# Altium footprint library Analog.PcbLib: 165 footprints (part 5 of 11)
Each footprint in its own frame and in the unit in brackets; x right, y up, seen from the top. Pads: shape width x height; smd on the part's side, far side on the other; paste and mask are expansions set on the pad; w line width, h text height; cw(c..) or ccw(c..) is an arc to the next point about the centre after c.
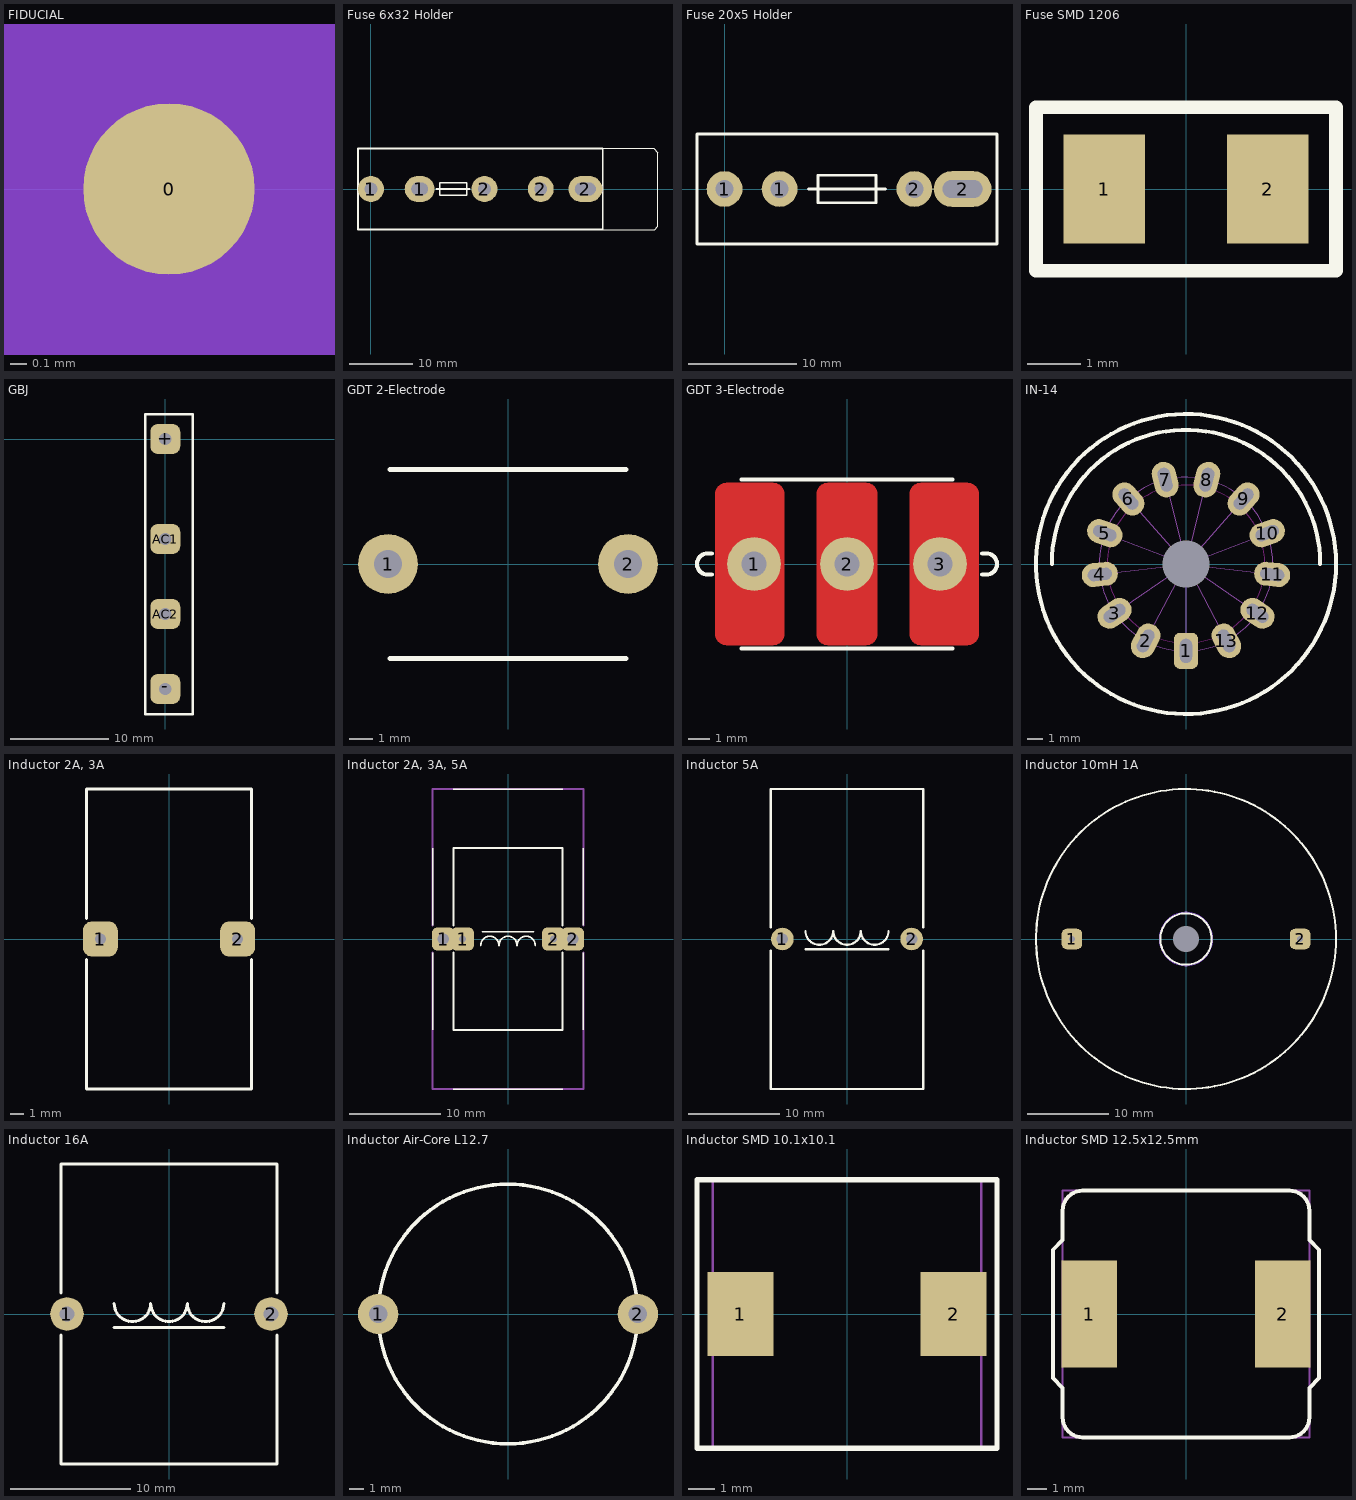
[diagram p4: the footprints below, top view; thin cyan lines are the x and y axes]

## FIDUCIAL [mil]
pads (1):
  round 40 all layers, no hole paste-40 mask+40: 0(0,0)
Top Layer keep-out:
  circle w50: c0,0 r35
Bottom Layer keep-out:
  circle w50: c0,0 r35

## Fuse 6x32 Holder [mil]
height 433.07
pads (5):
  round 160 hole 78: 1(0,0) 2(700,0) 2(1047,0)
  rrect100% 184x160 hole 78 slot 102 at 0 deg: 1(300,0)
  rrect100% 210x160 hole 78 slot 128 at 0 deg: 2(1322,0)
Top Overlay:
  lines w6: 1430,-250 1750,-250 1770,-230 1770,225 1745,250 1430,250
  lines w10: 403.54,0 610.24,0 ; -80,-250 1430,-250 1430,250 -80,250 -80,-250 ; 423.23,-39.37 423.23,39.37 590.55,39.37 590.55,-39.37 423.23,-39.37

## Fuse 20x5 Holder [mil]
pads (4):
  round 130 hole 65: 1(0,0) 1(200,0) 2(690,0)
  rrect100% 210x130 hole 65 slot 145 at 0 deg: 2(865,0)
Top Overlay:
  lines w10: 305,0 585,0 ; -100,-200 990,-200 990,200 -100,200 -100,-200 ; 340,-50 340,50 550,50 550,-50 340,-50

## Fuse SMD 1206 [mil]
pads (2):
  rect 60x80 smd: 1(-60,0) 2(60,0)
Top Overlay:
  lines w10: -110,-60 -110,0 -110,60 110,60 110,-60 -110,-60
Mechanical 13:
  lines w1: -110,-60 110,-60 110,60 -110,60 -110,-60
  text ".Designator" at -93,-17 h40

## GBJ [mil]
pads (4):
  rrect50% 120x120 hole 49: +(0,0) -(0,-1000) AC1(0,-400) AC2(0,-700)
Top Overlay:
  lines w10: -80,-1100 -80,100 110,100 110,-1100 -80,-1100

## GDT 2-Electrode [mm]
pads (2):
  round 2.54 hole 1.2: 1(-5.08,0) 2(5.08,0)
Top Overlay:
  lines w0.2: -5,-4 5,-4 ; -5,4 5,4

## GDT 3-Electrode [mm]
pads (3):
  round 2.54 hole 1.2: 1(-4.4,0) 2(0,0) 3(4.4,0)
Top Layer:
  region: -1.4,-3.3 -1.4,-3.399 -1.324,-3.583 -1.183,-3.724 -0.999,-3.8 -0.9,-3.8 0.9,-3.8 0.999,-3.8 1.183,-3.724 1.324,-3.583 1.4,-3.399 1.4,-3.3 1.4,3.3 1.4,3.399 1.324,3.583 1.183,3.724 0.999,3.8 0.9,3.8 -0.9,3.8 -0.999,3.8 -1.183,3.724 -1.324,3.583 -1.4,3.399 -1.4,3.3
  region: -6.2,-3.3 -6.2,3.3 -6.2,3.399 -6.124,3.583 -5.983,3.724 -5.799,3.8 -5.7,3.8 -3.5,3.8 -3.401,3.8 -3.217,3.724 -3.076,3.583 -3,3.399 -3,3.3 -3,-3.3 -3,-3.399 -3.076,-3.583 -3.217,-3.724 -3.401,-3.8 -3.5,-3.8 -5.7,-3.8 -5.799,-3.8 -5.983,-3.724 -6.124,-3.583 -6.2,-3.399
  region: 3,-3.3 3,3.3 3,3.399 3.076,3.583 3.217,3.724 3.401,3.8 3.5,3.8 5.7,3.8 5.799,3.8 5.983,3.724 6.124,3.583 6.2,3.399 6.2,3.3 6.2,-3.3 6.2,-3.399 6.124,-3.583 5.983,-3.724 5.799,-3.8 5.7,-3.8 3.5,-3.8 3.401,-3.8 3.217,-3.724 3.076,-3.583 3,-3.399
  lines w0.1: -6.2,-3.3 ccw(c-5.7,-3.3) -5.7,-3.8 -3.5,-3.8 ccw(c-3.5,-3.3) -3,-3.3 -3,3.3 ccw(c-3.5,3.3) -3.5,3.8 -5.7,3.8 ccw(c-5.7,3.3) -6.2,3.3 -6.2,-3.3 ; -1.4,-3.3 ccw(c-0.9,-3.3) -0.9,-3.8 0.9,-3.8 ccw(c0.9,-3.3) 1.4,-3.3 1.4,3.3 ccw(c0.9,3.3) 0.9,3.8 -0.9,3.8 ccw(c-0.9,3.3) -1.4,3.3 -1.4,-3.3 ; 3,-3.3 ccw(c3.5,-3.3) 3.5,-3.8 5.7,-3.8 ccw(c5.7,-3.3) 6.2,-3.3 6.2,3.3 ccw(c5.7,3.3) 5.7,3.8 3.5,3.8 ccw(c3.5,3.3) 3,3.3 3,-3.3
Top Overlay:
  lines w0.2: -6.4,-0.5 -6.6,-0.5 cw(c-6.6,0) -6.6,0.5 -6.4,0.5 ; -5,-4 5,-4 ; -5,4 5,4 ; 6.4,-0.5 6.6,-0.5 ccw(c6.6,0) 6.6,0.5 6.4,0.5

## IN-14 [mil] "IN-14 Nixie"
height 2145.67
pads (14):
  round 0 hole 118.11 unplated: 0(0,0)
  rrect50% 60x90 hole 30 slot 60 at 90 deg: 1(0,-216.54)
  oval 60x90 hole 30 slot 60 at 62.31 deg rot 152.31: 2(-100.63,-191.73)
  oval 60x90 hole 30 slot 60 at 34.6 deg rot 124.6: 3(-178.19,-122.99)
  oval 60x90 hole 30 slot 60 at 6.92 deg rot 96.92: 4(-214.95,-26.1)
  oval 60x90 hole 30 slot 60 at 159.23 deg rot 69.23: 5(-202.46,76.77)
  oval 60x90 hole 30 slot 60 at 131.54 deg rot 41.54: 6(-143.59,162.08)
  oval 60x90 hole 30 slot 60 at 103.85 deg rot 13.85: 7(-51.82,210.24)
  oval 60x90 hole 30 slot 60 at 76.15 deg rot 166.15: 8(51.82,210.24)
  oval 60x90 hole 30 slot 60 at 48.46 deg rot 138.46: 9(143.59,162.08)
  oval 60x90 hole 30 slot 60 at 20.77 deg rot 110.77: 10(202.46,76.78)
  oval 60x90 hole 30 slot 60 at 173.08 deg rot 83.08: 11(214.95,-26.1)
  oval 60x90 hole 30 slot 60 at 145.39 deg rot 55.39: 12(178.2,-123)
  oval 60x90 hole 30 slot 60 at 117.7 deg rot 27.7: 13(100.63,-191.73)
Top Overlay:
  circle w10: c0,0 r374.02
  lines w10: -334.65,0 cw(c0,0) 334.65,0
Bottom Overlay:
  lines w8: -19.68,259.84 0,240.16 ; 0,314.96 0,240.16 ; 19.68,259.84 0,240.16
Keep-Out Layer:
  circle w2: c0,0 r196.85
Mechanical 13:
  circle w1: c0,0 r216.54
  lines w1: -214.95,-26.1 0,0 ; -202.46,76.78 0,0 ; -178.19,-122.99 0,0 ; -143.59,162.08 0,0 ; -100.59,-191.73 0,0 ; -51.82,210.24 0,0 ; 0,-216.54 0,0 ; 51.82,210.24 0,0 ; 100.63,-191.73 0,0 ; 143.59,162.08 0,0 ; 178.2,-123 0,0 ; 202.46,76.78 0,0 ; 214.95,-26.1 0,0

## Inductor 2A, 3A [mm]
height 30
pads (2):
  rrect50% 2.54x2.54 hole 0.8: 1(-5,0) 2(5,0)
Top Overlay:
  lines w0.2: -6,-1.5 -6,-10.922 6,-10.922 6,-1.5 ; -6,1.5 -6,10.922 6,10.922 6,1.5

## Inductor 2A, 3A, 5A [mil]
height 1181.1
pads (4):
  rrect50% 100x100 hole 49: 1(-280,0) 2(280,0)
  rrect50% 100x100 hole 31.5: 1(-196.85,0) 2(196.85,0)
Top Overlay:
  lines w6: -326.77,-393.7 -326.77,-59.06 ; -326.77,59.06 -326.77,393.7 ; -236.22,-649.61 236.22,-649.61 ; -236.22,649.61 236.22,649.61 ; 326.77,-393.7 326.77,-59.06 ; 326.77,59.06 326.77,393.7
  lines w7.87: -236.22,-59.06 -236.22,-393.7 236.22,-393.7 236.22,-59.06 ; -236.22,59.06 -236.22,393.7 236.22,393.7 236.22,59.06 ; -118.11,-27.56 cw(c-78.74,-27.56) -39.37,-27.56 cw(c0,-27.56) 39.37,-27.56 cw(c78.74,-27.56) 118.11,-27.56 ; -110.24,31.5 110.24,31.5
Mechanical 13:
  lines w10: -326.77,-59.06 -326.77,-649.61 326.77,-649.61 326.77,-59.06 ; -326.77,59.06 -326.77,649.61 326.77,649.61 326.77,59.06

## Inductor 5A [mil]
pads (2):
  round 98 hole 49: 1(-280,0) 2(280,0)
Top Overlay:
  lines w10: -330,-50 -330,-650 330,-650 330,-50 ; -330,50 -330,650 330,650 330,50 ; -180,-45 180,-45 ; -180,35 ccw(c-120,35) -60,35 ccw(c0,35) 60,35 ccw(c120,35) 180,35

## Inductor 10mH 1A [mil]
height 1030
pads (3):
  round 0 hole 126 unplated mask+120: 0(0,0)
  rrect50% 100x100 hole 30: 1(-555,0) 2(555,0)
Top Layer keep-out:
  circle w6: c0,0 r130
Bottom Layer keep-out:
  circle w6: c0,0 r130
Top Overlay:
  circle w10: c0,0 r125
  circle w10: c0,0 r730
Bottom Overlay:
  circle w10: c0,0 r125

## Inductor 16A [mil]
pads (2):
  round 110 hole 50: 1(-334.65,0) 2(334.65,0)
Top Overlay:
  lines w10: -354.33,-68.9 -354.33,-492.13 354.33,-492.13 354.33,-68.9 ; -354.33,68.9 -354.33,492.13 354.33,492.13 354.33,68.9 ; -180,-45 180,-45 ; -180,35 ccw(c-120,35) -60,35 ccw(c0,35) 60,35 ccw(c120,35) 180,35

## Inductor Air-Core L12.7 [mil]
height 866.14
pads (2):
  round 110 hole 50: 1(-354.33,0) 2(354.33,0)
Top Overlay:
  circle w10: c0,0 r354.33

## Inductor SMD 10.1x10.1 [mm]
pads (2):
  rect 2.5x3.2 smd: 1(-4.05,0) 2(4.05,0)
Top Overlay:
  lines w0.2: -5.7,-5.1 -5.7,5.1 5.7,5.1 5.7,-5.1 -5.7,-5.1
Mechanical 13:
  lines w0.1: -5.1,-5.1 -5.1,5.1 5.1,5.1 5.1,-5.1 -5.1,-5.1
  text ".Designator" at 0.3,-3.9 h0.89

## Inductor SMD 12.5x12.5mm [mm]
height 12
pads (2):
  rect 2.8x5.4 smd: 1(-4.9,0) 2(4.9,0)
Top Overlay:
  lines w0.2: -6.75,3.25 -6.25,3.75 -6.25,5.25 cw(c-5.25,5.25) -5.25,6.25 5.25,6.25 cw(c5.25,5.25) 6.25,5.25 6.25,3.75 6.75,3.25 ; -6.25,-5.25 ccw(c-5.25,-5.25) -5.25,-6.25 5.25,-6.25 ccw(c5.25,-5.25) 6.25,-5.25
  lines w0.203: -6.75,3.25 -6.75,-3.25 -6.25,-3.75 -6.25,-5.25 ; 6.25,-5.25 6.25,-3.75 6.75,-3.25 6.75,3.25
Mechanical 13:
  lines w0.1: -6.25,-6.25 -6.25,6.25 6.25,6.25 6.25,-6.25 -6.25,-6.25
  text ".Designator" at 0.3,-3.9 h0.89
